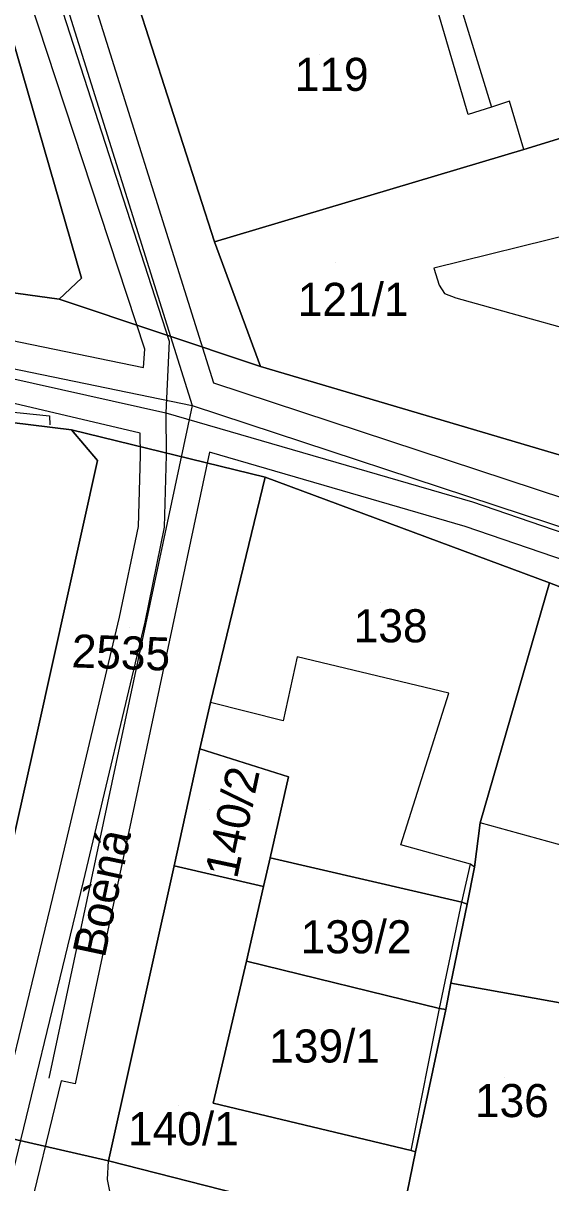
# Model space of a CAD drawing. Extents: x -263423 to -261326, y -1240067 to -1237864.
# Drawn here: x -262878.1 to -262846.2, y -1239820.5 to -1239750.4 of the extents above; entities that cross this region are included whole.
import ezdxf

# ---------------------------------------------------------------- set-up
doc = ezdxf.new("R2010")
doc.units = 0
for name, color, linetype in [('body_kn', 7, 'Continuous'), ('kladpar_druhypozemkov', 7, 'Continuous'), ('kladpar_hranice', 7, 'Continuous'), ('kladpar_parcelnecisla', 7, 'Continuous'), ('kladpar_plochy', 7, 'Continuous'), ('popisy', 7, 'Continuous'), ('tarchy_linie', 7, 'Continuous'), ('zappar_hrandruhpozemk', 7, 'Continuous')]:
    doc.layers.add(name, color=color, linetype=linetype)

msp = doc.modelspace()

# ---------------------------------------------------------------- linework, layer by layer
at = {"layer": 'body_kn'}
for p, q in [((-262849.77, -1239755.46), (-262849.77, -1239755.46)), ((-262848.69, -1239755.08), (-262848.69, -1239755.08)), ((-262851.18, -1239755.9), (-262851.18, -1239755.9)), ((-262847.81, -1239758.02), (-262847.81, -1239758.02)), ((-262847.81, -1239758.02), (-262847.81, -1239758.02)), ((-262866.5, -1239763.6), (-262866.5, -1239763.6)), ((-262853.25, -1239765.19), (-262853.25, -1239765.19)), ((-262874.54, -1239765.79), (-262874.54, -1239765.79)), ((-262852.94, -1239766.21), (-262852.94, -1239766.21)), ((-262852.62, -1239766.72), (-262852.62, -1239766.72)), ((-262851.92, -1239766.98), (-262851.92, -1239766.98)), ((-262875.89, -1239767.06), (-262875.89, -1239767.06)), ((-262869.24, -1239769.6), (-262869.24, -1239769.6)), ((-262870.71, -1239770.08), (-262870.71, -1239770.08)), ((-262863.73, -1239771.13), (-262863.73, -1239771.13)), ((-262870.8, -1239771.19), (-262870.8, -1239771.19)), ((-262866.56, -1239772.12), (-262866.56, -1239772.12)), ((-262869.45, -1239773.93), (-262869.45, -1239773.93)), ((-262867.86, -1239773.48), (-262867.86, -1239773.48)), ((-262876.48, -1239774.11), (-262876.48, -1239774.11)), ((-262876.45, -1239774.65), (-262876.45, -1239774.65)), ((-262875.15, -1239774.96), (-262875.15, -1239774.96)), ((-262870.99, -1239775.16), (-262870.99, -1239775.16)), ((-262870.98, -1239776.5), (-262870.98, -1239776.5)), ((-262869.43, -1239776.49), (-262869.43, -1239776.49)), ((-262866.8, -1239776.31), (-262866.8, -1239776.31)), ((-262873.57, -1239776.82), (-262873.57, -1239776.82)), ((-262863.44, -1239777.82), (-262863.44, -1239777.82)), ((-262863.44, -1239777.82), (-262863.44, -1239777.82)), ((-262850.93, -1239779.31), (-262850.93, -1239779.31)), ((-262871.1, -1239780.79), (-262871.1, -1239780.79)), ((-262869.55, -1239780.83), (-262869.55, -1239780.83)), ((-262851.36, -1239780.8), (-262851.36, -1239780.8)), ((-262846.26, -1239784.21), (-262846.26, -1239784.21)), ((-262846.26, -1239784.21), (-262846.26, -1239784.21)), ((-262872.24, -1239786.27), (-262872.24, -1239786.27)), ((-262870.72, -1239786.58), (-262870.72, -1239786.58)), ((-262861.51, -1239788.67), (-262861.51, -1239788.67)), ((-262866.74, -1239791.44), (-262866.74, -1239791.44)), ((-262852.34, -1239790.88), (-262852.34, -1239790.88)), ((-262862.35, -1239792.55), (-262862.35, -1239792.55)), ((-262877.2, -1239793.18), (-262877.2, -1239793.18)), ((-262867.39, -1239794.24), (-262867.39, -1239794.24)), ((-262862.04, -1239795.93), (-262862.04, -1239795.93)), ((-262862.04, -1239795.93), (-262862.04, -1239795.93)), ((-262850.46, -1239798.72), (-262850.46, -1239798.72)), ((-262855.24, -1239800.04), (-262855.24, -1239800.04)), ((-262868.95, -1239801.31), (-262868.95, -1239801.31)), ((-262863.15, -1239800.83), (-262863.15, -1239800.83)), ((-262851.04, -1239801.2), (-262851.04, -1239801.2)), ((-262875.95, -1239801.89), (-262875.95, -1239801.89)), ((-262850.79, -1239801.4), (-262850.79, -1239801.4)), ((-262850.79, -1239801.4), (-262850.79, -1239801.4)), ((-262874.44, -1239802.25), (-262874.44, -1239802.25)), ((-262863.54, -1239802.55), (-262863.54, -1239802.55)), ((-262863.54, -1239802.55), (-262863.54, -1239802.55)), ((-262851.56, -1239803.5), (-262851.56, -1239803.5)), ((-262851.56, -1239803.5), (-262851.56, -1239803.5)), ((-262851.24, -1239803.63), (-262851.24, -1239803.63)), ((-262864.58, -1239807.07), (-262864.58, -1239807.07)), ((-262852.22, -1239808.4), (-262852.22, -1239808.4)), ((-262852.92, -1239809.93), (-262852.92, -1239809.93)), ((-262852.92, -1239809.93), (-262852.92, -1239809.93)), ((-262852.54, -1239809.99), (-262852.54, -1239809.99)), ((-262876.52, -1239814.15), (-262876.52, -1239814.15)), ((-262875.78, -1239814.31), (-262875.78, -1239814.31)), ((-262874.93, -1239814.49), (-262874.93, -1239814.49)), ((-262866.59, -1239815.66), (-262866.59, -1239815.66)), ((-262854.62, -1239818.52), (-262854.62, -1239818.52)), ((-262854.62, -1239818.52), (-262854.62, -1239818.52)), ((-262854.36, -1239818.59), (-262854.36, -1239818.59)), ((-262872.91, -1239819.14), (-262872.91, -1239819.14)), ((-262872.98, -1239820.28), (-262872.98, -1239820.28))]:
    msp.add_line(p, q, dxfattribs=at)
at = {"layer": 'kladpar_druhypozemkov'}
for p, q in [((-262860.18, -1239752.27), (-262860.18, -1239752.27)), ((-262859.18, -1239764.87), (-262859.18, -1239764.87)), ((-262856.48, -1239785.4), (-262856.48, -1239785.4)), ((-262871.67, -1239786.93), (-262871.67, -1239786.93)), ((-262866.78, -1239797.9), (-262866.78, -1239797.9)), ((-262857.56, -1239805.18), (-262857.56, -1239805.18)), ((-262860.18, -1239811.2), (-262860.18, -1239811.2)), ((-262848.98, -1239814.1), (-262848.98, -1239814.1)), ((-262868.68, -1239815.8), (-262868.68, -1239815.8))]:
    msp.add_line(p, q, dxfattribs=at)
at = {"layer": 'kladpar_hranice'}
for points in [[(-262850.1, -1239741.76), (-262846.21, -1239740.44), (-262836.07, -1239737.75), (-262834.85, -1239737.5), (-262832.24, -1239736.87), (-262832.49, -1239735.72), (-262830.38, -1239735.03), (-262828.56, -1239740.52), (-262827.55, -1239743.84), (-262825.28, -1239750.86), (-262828.98, -1239751.93), (-262832.05, -1239752.87), (-262833.96, -1239753.43), (-262833.9, -1239753.75), (-262845, -1239757.14), (-262847.81, -1239758.02), (-262866.5, -1239763.6), (-262871.23, -1239748.86), (-262861.27, -1239745.65), (-262850.1, -1239741.76)], [(-262871.23, -1239748.86), (-262866.5, -1239763.6), (-262863.73, -1239771.13), (-262875.89, -1239767.06), (-262874.54, -1239765.79), (-262878.76, -1239751.18), (-262879.51, -1239748.5)], [(-262878.76, -1239751.18), (-262874.54, -1239765.79), (-262875.89, -1239767.06), (-262885.38, -1239765.74), (-262888.27, -1239756.29), (-262878.76, -1239751.18)], [(-262847.81, -1239758.02), (-262845, -1239757.14), (-262833.9, -1239753.75), (-262833.96, -1239753.43), (-262832.05, -1239752.87), (-262830.86, -1239758.73), (-262826.39, -1239757.29), (-262825.58, -1239760.29), (-262825.51, -1239760.61), (-262831.38, -1239761.6), (-262830.76, -1239765.3), (-262830.2, -1239768.68), (-262838.81, -1239770.17), (-262838.87, -1239770.61), (-262838.39, -1239778.64), (-262841, -1239777.87), (-262843.17, -1239777.22), (-262863.73, -1239771.13), (-262866.5, -1239763.6), (-262847.81, -1239758.02)], [(-262915.95, -1239758.58), (-262900.47, -1239762.41), (-262895.61, -1239763.35), (-262891.3, -1239764.18), (-262885.38, -1239765.74), (-262875.89, -1239767.06), (-262863.73, -1239771.13), (-262843.17, -1239777.22)], [(-262837.73, -1239787.5), (-262846.26, -1239784.21), (-262863.44, -1239777.82), (-262875.15, -1239774.96), (-262884.84, -1239773.77), (-262889.93, -1239772.73), (-262900.95, -1239770.38), (-262906.43, -1239769.14), (-262913.56, -1239767.45), (-262924.71, -1239764.46), (-262930.7, -1239763.1)], [(-262884.84, -1239773.77), (-262875.15, -1239774.96), (-262873.57, -1239776.82), (-262877.2, -1239793.18), (-262882.14, -1239815.14), (-262884.44, -1239816.6), (-262894.18, -1239814.19), (-262891.2, -1239802.03), (-262888.28, -1239789.24), (-262884.84, -1239773.77)], [(-262863.44, -1239777.82), (-262866.74, -1239791.44), (-262867.39, -1239794.24), (-262868.95, -1239801.31), (-262872.91, -1239819.14), (-262882.59, -1239816.92), (-262882.14, -1239815.14), (-262877.2, -1239793.18), (-262873.57, -1239776.82), (-262875.15, -1239774.96), (-262863.44, -1239777.82)], [(-262846.26, -1239784.21), (-262850.46, -1239798.72), (-262850.79, -1239801.4), (-262851.24, -1239803.63), (-262851.56, -1239803.5), (-262863.15, -1239800.83), (-262862.04, -1239795.93), (-262867.39, -1239794.24), (-262866.74, -1239791.44), (-262863.44, -1239777.82), (-262846.26, -1239784.21)], [(-262846.26, -1239784.21), (-262837.73, -1239787.5), (-262841.42, -1239801.19), (-262842.33, -1239805.51), (-262843.17, -1239810.04), (-262852.22, -1239808.4), (-262851.24, -1239803.63), (-262850.79, -1239801.4), (-262850.46, -1239798.72), (-262846.26, -1239784.21)], [(-262862.04, -1239795.93), (-262863.15, -1239800.83), (-262863.54, -1239802.55), (-262868.95, -1239801.31), (-262867.39, -1239794.24), (-262862.04, -1239795.93)], [(-262863.54, -1239802.55), (-262864.58, -1239807.07), (-262866.59, -1239815.66), (-262854.62, -1239818.52), (-262854.36, -1239818.59), (-262855.4, -1239823.62), (-262872.91, -1239819.14), (-262868.95, -1239801.31), (-262863.54, -1239802.55)], [(-262851.56, -1239803.5), (-262851.24, -1239803.63), (-262852.22, -1239808.4), (-262852.54, -1239809.99), (-262852.92, -1239809.93), (-262864.58, -1239807.07), (-262863.54, -1239802.55), (-262863.15, -1239800.83), (-262851.56, -1239803.5)], [(-262852.92, -1239809.93), (-262852.54, -1239809.99), (-262854.36, -1239818.59), (-262854.62, -1239818.52), (-262866.59, -1239815.66), (-262864.58, -1239807.07), (-262852.92, -1239809.93)], [(-262947.85, -1239809.79), (-262945.55, -1239809.61), (-262941.85, -1239809.44), (-262937.9, -1239809.08), (-262935.03, -1239808.9), (-262929.16, -1239808.4), (-262927.24, -1239808.23), (-262923.23, -1239808), (-262915.57, -1239807.72), (-262910.04, -1239809.4), (-262894.18, -1239814.19), (-262884.44, -1239816.6), (-262882.14, -1239815.14), (-262882.59, -1239816.92), (-262872.91, -1239819.14), (-262855.4, -1239823.62)], [(-262843.17, -1239810.04), (-262844.22, -1239815.57), (-262844.79, -1239818.5), (-262846.17, -1239825.51), (-262846.23, -1239825.82), (-262855.4, -1239823.62), (-262854.36, -1239818.59), (-262852.54, -1239809.99), (-262852.22, -1239808.4), (-262843.17, -1239810.04)]]:
    msp.add_lwpolyline(points, dxfattribs=at)
at = {"layer": 'kladpar_plochy'}
for points in [[(-262850.1, -1239741.76), (-262846.21, -1239740.44), (-262836.07, -1239737.75), (-262834.85, -1239737.5), (-262832.24, -1239736.87), (-262832.49, -1239735.72), (-262830.38, -1239735.03), (-262828.56, -1239740.52), (-262827.55, -1239743.84), (-262825.28, -1239750.86), (-262828.98, -1239751.93), (-262832.05, -1239752.87), (-262833.96, -1239753.43), (-262833.9, -1239753.75), (-262845, -1239757.14), (-262847.81, -1239758.02), (-262866.5, -1239763.6), (-262871.23, -1239748.86), (-262861.27, -1239745.65)], [(-262878.76, -1239751.18), (-262874.54, -1239765.79), (-262875.89, -1239767.06), (-262885.38, -1239765.74), (-262888.27, -1239756.29)], [(-262847.81, -1239758.02), (-262845, -1239757.14), (-262833.9, -1239753.75), (-262833.96, -1239753.43), (-262832.05, -1239752.87), (-262830.86, -1239758.73), (-262826.39, -1239757.29), (-262825.58, -1239760.29), (-262825.51, -1239760.61), (-262831.38, -1239761.6), (-262830.76, -1239765.3), (-262830.2, -1239768.68), (-262838.81, -1239770.17), (-262838.87, -1239770.61), (-262838.39, -1239778.64), (-262841, -1239777.87), (-262843.17, -1239777.22), (-262863.73, -1239771.13), (-262866.5, -1239763.6)], [(-262884.84, -1239773.77), (-262875.15, -1239774.96), (-262873.57, -1239776.82), (-262877.2, -1239793.18), (-262882.14, -1239815.14), (-262884.44, -1239816.6), (-262894.18, -1239814.19), (-262891.2, -1239802.03), (-262888.28, -1239789.24)], [(-262863.44, -1239777.82), (-262866.74, -1239791.44), (-262867.39, -1239794.24), (-262868.95, -1239801.31), (-262872.91, -1239819.14), (-262882.59, -1239816.92), (-262882.14, -1239815.14), (-262877.2, -1239793.18), (-262873.57, -1239776.82), (-262875.15, -1239774.96)], [(-262846.26, -1239784.21), (-262850.46, -1239798.72), (-262850.79, -1239801.4), (-262851.24, -1239803.63), (-262851.56, -1239803.5), (-262863.15, -1239800.83), (-262862.04, -1239795.93), (-262867.39, -1239794.24), (-262866.74, -1239791.44), (-262863.44, -1239777.82)], [(-262846.26, -1239784.21), (-262837.73, -1239787.5), (-262841.42, -1239801.19), (-262842.33, -1239805.51), (-262843.17, -1239810.04), (-262852.22, -1239808.4), (-262851.24, -1239803.63), (-262850.79, -1239801.4), (-262850.46, -1239798.72)], [(-262862.04, -1239795.93), (-262863.15, -1239800.83), (-262863.54, -1239802.55), (-262868.95, -1239801.31), (-262867.39, -1239794.24)], [(-262863.54, -1239802.55), (-262864.58, -1239807.07), (-262866.59, -1239815.66), (-262854.62, -1239818.52), (-262854.36, -1239818.59), (-262855.4, -1239823.62), (-262872.91, -1239819.14), (-262868.95, -1239801.31)], [(-262851.56, -1239803.5), (-262851.24, -1239803.63), (-262852.22, -1239808.4), (-262852.54, -1239809.99), (-262852.92, -1239809.93), (-262864.58, -1239807.07), (-262863.54, -1239802.55), (-262863.15, -1239800.83)], [(-262852.92, -1239809.93), (-262852.54, -1239809.99), (-262854.36, -1239818.59), (-262854.62, -1239818.52), (-262866.59, -1239815.66), (-262864.58, -1239807.07)], [(-262843.17, -1239810.04), (-262844.22, -1239815.57), (-262844.79, -1239818.5), (-262846.17, -1239825.51), (-262846.23, -1239825.82), (-262855.4, -1239823.62), (-262854.36, -1239818.59), (-262852.54, -1239809.99), (-262852.22, -1239808.4)]]:
    msp.add_lwpolyline(points, close=True, dxfattribs=at)
for points in [[(-262871.23, -1239748.86), (-262866.5, -1239763.6), (-262863.73, -1239771.13), (-262875.89, -1239767.06), (-262874.54, -1239765.79), (-262878.76, -1239751.18), (-262879.51, -1239748.5)], [(-262930.66, -1239755), (-262915.95, -1239758.58), (-262900.47, -1239762.41), (-262895.61, -1239763.35), (-262891.3, -1239764.18), (-262885.38, -1239765.74), (-262875.89, -1239767.06), (-262863.73, -1239771.13), (-262843.17, -1239777.22)], [(-262837.73, -1239787.5), (-262846.26, -1239784.21), (-262863.44, -1239777.82), (-262875.15, -1239774.96), (-262884.84, -1239773.77), (-262889.93, -1239772.73), (-262900.95, -1239770.38), (-262906.43, -1239769.14), (-262913.56, -1239767.45), (-262924.71, -1239764.46), (-262930.7, -1239763.1)], [(-262929.16, -1239808.4), (-262927.24, -1239808.23), (-262923.23, -1239808), (-262915.57, -1239807.72), (-262910.04, -1239809.4), (-262894.18, -1239814.19), (-262884.44, -1239816.6), (-262882.14, -1239815.14), (-262882.59, -1239816.92), (-262872.91, -1239819.14), (-262855.4, -1239823.62)]]:
    msp.add_lwpolyline(points, dxfattribs=at)
at = {"layer": 'tarchy_linie'}
for points in [[(-262915.65, -1239632.76), (-262911.73, -1239641.19), (-262896.19, -1239689.65), (-262885, -1239718.92), (-262867.86, -1239773.48), (-262876.52, -1239814.15)], [(-262915.03, -1239632.68), (-262910.87, -1239648.29), (-262908.18, -1239655.98), (-262898.63, -1239684.9), (-262893.91, -1239697.85), (-262885.92, -1239718.95), (-262875.9, -1239749.03), (-262869.24, -1239769.6), (-262869.45, -1239773.93), (-262869.43, -1239776.49), (-262869.55, -1239780.83), (-262870.72, -1239786.58), (-262874.44, -1239802.25), (-262879.48, -1239822.97)], [(-263076.78, -1239674.94), (-263067.73, -1239689.43), (-263061.59, -1239698.97), (-263048.27, -1239722.8), (-262993, -1239743.37), (-262958.92, -1239752.71), (-262923.54, -1239762), (-262867.86, -1239773.48), (-262824.56, -1239787.75), (-262785.95, -1239791.48), (-262742.38, -1239779.12)], [(-262897.38, -1239680.53), (-262894.62, -1239689.15), (-262883.46, -1239718.33), (-262866.56, -1239772.12), (-262824.03, -1239786.14)], [(-262958.48, -1239751.12), (-262923.12, -1239760.4), (-262870.8, -1239771.19), (-262870.71, -1239770.08), (-262887.37, -1239719.5), (-262895.37, -1239698.38), (-262900.1, -1239685.39)], [(-262940.14, -1239759.32), (-262928.37, -1239762.28), (-262917.86, -1239764.95), (-262902.23, -1239768.95), (-262884.95, -1239770.75), (-262884.36, -1239770.87), (-262883.78, -1239770.73), (-262869.45, -1239773.93), (-262850.93, -1239779.31), (-262843.22, -1239781.94), (-262829.93, -1239786.66), (-262823.34, -1239788.76), (-262817.45, -1239789.44), (-262809.15, -1239790.52), (-262788.88, -1239792.15), (-262785.42, -1239792.12), (-262780.73, -1239791.05), (-262756.46, -1239784.2), (-262753.28, -1239783.31), (-262752.8, -1239783.37), (-262751.64, -1239783.07), (-262742.08, -1239779.91)], [(-262880.99, -1239822.6), (-262875.95, -1239801.89), (-262872.24, -1239786.27), (-262871.1, -1239780.79), (-262870.98, -1239776.5), (-262870.99, -1239775.16), (-262883.42, -1239772.24), (-262884.67, -1239772.39), (-262885.11, -1239772.29), (-262898.69, -1239770.86), (-262900.95, -1239770.38), (-262906.43, -1239769.14), (-262913.56, -1239767.45), (-262924.71, -1239764.46), (-262930.7, -1239763.1)], [(-262900.27, -1239770.28), (-262894.42, -1239771.43), (-262885.95, -1239772.97), (-262883.46, -1239773.46), (-262881.61, -1239773.59), (-262876.48, -1239774.11), (-262876.45, -1239774.65)], [(-262843.72, -1239783.41), (-262851.36, -1239780.8), (-262866.8, -1239776.31), (-262874.93, -1239814.49), (-262875.78, -1239814.31), (-262877.97, -1239823.34)]]:
    msp.add_lwpolyline(points, dxfattribs=at)
at = {"layer": 'zappar_hrandruhpozemk'}
for p, q in [((-262852.79, -1239745.63), (-262849.77, -1239755.46)), ((-262851.18, -1239755.9), (-262854.07, -1239746.07)), ((-262830.67, -1239759.56), (-262853.25, -1239765.19)), ((-262852.34, -1239790.88), (-262861.51, -1239788.67)), ((-262841.42, -1239801.19), (-262850.46, -1239798.72)), ((-262851.56, -1239803.5), (-262851.04, -1239801.2)), ((-262852.92, -1239809.93), (-262851.56, -1239803.5)), ((-262854.62, -1239818.52), (-262852.92, -1239809.93))]:
    msp.add_line(p, q, dxfattribs=at)
for points in [[(-262847.81, -1239758.02), (-262848.69, -1239755.08), (-262849.77, -1239755.46), (-262851.18, -1239755.9)], [(-262853.25, -1239765.19), (-262852.94, -1239766.21), (-262852.62, -1239766.72), (-262851.92, -1239766.98), (-262841.23, -1239769.96), (-262838.87, -1239770.61)], [(-262861.51, -1239788.67), (-262862.35, -1239792.55), (-262866.74, -1239791.44)], [(-262850.79, -1239801.4), (-262851.04, -1239801.2), (-262855.24, -1239800.04), (-262852.34, -1239790.88)], [(-262872.09, -1239821.88), (-262872.79, -1239821.18), (-262872.98, -1239820.28), (-262872.91, -1239819.14)]]:
    msp.add_lwpolyline(points, dxfattribs=at)

# ---------------------------------------------------------------- texts
at = {"layer": 'kladpar_parcelnecisla'}
for s, p in [('119', (-262861.66, -1239754.47)), ('121/1', (-262861.477, -1239768.07)), ('138', (-262858.096, -1239787.8)), ('139/2', (-262861.299, -1239806.6)), ('139/1', (-262863.203, -1239813.2)), ('136', (-262850.772, -1239816.5)), ('140/1', (-262871.732, -1239818.2))]:
    msp.add_text(s, height=2, dxfattribs=at).set_placement(p)
for s, rotation, p in [('2535', 358, (-262875.162, -1239789.31)), ('140/2', 78, (-262865.151, -1239802.144))]:
    msp.add_text(s, height=2, rotation=rotation, dxfattribs=at).set_placement(p)
at = {"layer": 'popisy'}
msp.add_text('Boèná', height=2, rotation=78, dxfattribs=at).set_placement((-262873.141, -1239806.928))

doc.saveas('drawing.dxf')
